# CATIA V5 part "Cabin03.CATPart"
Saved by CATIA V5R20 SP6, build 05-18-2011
Part number: Cabin03
Bounding box of the stored display mesh (mm): x -721.019 to -578.019, y 0 to 20, z 1145 to 1385
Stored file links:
  E:\#01 CATIA Lecture Materials\#06 DMU\#01 DMU KIN Page01 EX01\#01 CATPart\Cabin03.CATPart
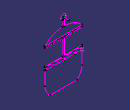
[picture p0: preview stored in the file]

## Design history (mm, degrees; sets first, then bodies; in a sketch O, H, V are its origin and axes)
AxisSystem1: origin (-649.5191, 0, 1375), X (1, 0, 0), Y (0, 1, 0), Z (0, 0, 1)
Set1
  DatumCurve1 "Curve.1 ( *CRV71 - wsp *MASTER -  )"
  DatumCurve2 "Curve.2 ( *CRV72 - wsp *MASTER -  )"
  DatumCurve3 "Curve.3 ( *CRV73 - wsp *MASTER -  )"
  DatumCurve4 "Curve.4 ( *CRV74 - wsp *MASTER -  )"
  DatumCurve5 "Curve.5 ( *CRV75 - wsp *MASTER -  )"
  DatumCurve6 "Curve.6 ( *CRV76 - wsp *MASTER -  )"
  DatumCurve7 "Curve.7 ( *CRV77 - wsp *MASTER -  )"
  DatumCurve8 "Curve.8 ( *CRV78 - wsp *MASTER -  )"
  DatumCurve9 "Curve.9 ( *CRV79 - wsp *MASTER -  )"
  DatumCurve10 "Curve.10 ( *CRV80 - wsp *MASTER -  )"
  DatumCurve11 "Curve.11 ( *CRV81 - wsp *MASTER -  )"
  DatumCurve12 "Curve.12 ( *CRV82 - wsp *MASTER -  )"
  DatumCurve13 "Curve.13 ( *CRV83 - wsp *MASTER -  )"
  DatumCurve14 "Curve.14 ( *CRV84 - wsp *MASTER -  )"
  DatumCurve15 "Curve.15 ( *CRV85 - wsp *MASTER -  )"
  DatumCurve16 "Curve.16 ( *CRV86 - wsp *MASTER -  )"
  DatumCurve17 "Curve.17 ( *CRV87 - wsp *MASTER -  )"
  Line1 "Line.1 ( *LN143 - wsp *MASTER -  )": stored without definition
  Line2 "Line.2 ( *LN144 - wsp *MASTER -  )": stored without definition
  Line3 "Line.3 ( *LN145 - wsp *MASTER -  )": stored without definition
  Line4 "Line.4 ( *LN146 - wsp *MASTER -  )": stored without definition
  Line5 "Line.5 ( *LN147 - wsp *MASTER -  )": stored without definition
  Line6 "Line.6 ( *LN148 - wsp *MASTER -  )": stored without definition
  Line7 "Line.7 ( *LN149 - wsp *MASTER -  )": stored without definition
  Line8 "Line.8 ( *LN150 - wsp *MASTER -  )": stored without definition
  Line9 "Line.9 ( *LN151 - wsp *MASTER -  )": stored without definition
  Line10 "Line.10 ( *LN152 - wsp *MASTER -  )": stored without definition
  Line11 "Line.11 ( *LN153 - wsp *MASTER -  )": stored without definition
  Line12 "Line.12 ( *LN154 - wsp *MASTER -  )": stored without definition
  Line13 "Line.13 ( *LN155 - wsp *MASTER -  )": stored without definition
  Line14 "Line.14 ( *LN156 - wsp *MASTER -  )": stored without definition
  Line15 "Line.15 ( *LN157 - wsp *MASTER -  )": stored without definition
  Line16 "Line.16 ( *LN158 - wsp *MASTER -  )": stored without definition
  Line17 "Line.17 ( *LN159 - wsp *MASTER -  )": stored without definition
  Line18 "Line.18 ( *LN160 - wsp *MASTER -  )": stored without definition
  Line19 "Line.19 ( *LN161 - wsp *MASTER -  )": stored without definition
  Line20 "Line.20 ( *LN162 - wsp *MASTER -  )": stored without definition
  Line21 "Line.21 ( *LN163 - wsp *MASTER -  )": stored without definition
  Line22 "Line.22 ( *LN164 - wsp *MASTER -  )": stored without definition
  Line23 "Line.23 ( *LN165 - wsp *MASTER -  )": stored without definition
  Line24 "Line.24 ( *LN166 - wsp *MASTER -  )": stored without definition
  Line25 "Line.25 ( *LN167 - wsp *MASTER -  )": stored without definition
  Line26 "Line.26 ( *LN168 - wsp *MASTER -  )": stored without definition
  Line27 "Line.27 ( *LN169 - wsp *MASTER -  )": stored without definition
  Line28 "Line.28 ( *LN170 - wsp *MASTER -  )": stored without definition
  Line29 "Line.29 ( *LN171 - wsp *MASTER -  )": stored without definition
  Line30 "Line.30 ( *LN172 - wsp *MASTER -  )": stored without definition
  Line31: stored without definition
  Point1: type OnCurve, Support Line25, Ratio 1
  Point2 "Point.5 ( PT5 - wsp *MASTER -  )": stored without definition
Body1 (main body)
